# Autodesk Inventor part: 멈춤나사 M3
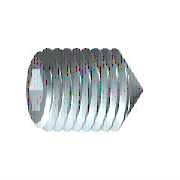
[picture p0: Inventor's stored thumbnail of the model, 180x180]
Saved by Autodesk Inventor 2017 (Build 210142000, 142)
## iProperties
Created: 2012-02
Part Number: 멈춤나사 M3
Material: 강철, 연강
Description: 6각 소켓 머리 없는 멈춤 나사
Document SubType Name: Modeling
Standard: KS B 1028
Designer: mduedu
Standards Organization: KS
Language: ko-KR
Size Designation: 원추점 M3x8
Categories: <MemberInstance><Categories><Category DisplayName="조임쇠" InternalName="e4da775c-781d-43d5-af7c-5136215cf5a6" Mnemonic="FSTN"><Category DisplayName="볼트" InternalN
Density: 7.86 g/cm^3
Mass: 0.360339 g
Surface Area: 0.888172 cm^2
Volume: 0.0458447 cm^3
Appearance: 강철
IsCustomPart: 1
Author: mduedu
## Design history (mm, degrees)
sketch "스케치1"
  geometry: L1 (0, 0)-(5.5, 0); L2 (8, 0.866)-(8, 1.5); L3 (8, 1.5)-(0, 1.5); L4 (8, 0.866)-(6, 0.866); L5 (6, 0.866)-(5.5, 0); L6 (0, -0.3)-(0, 1.8) reference; L7 (0, 1.5)-(0, 0)
  constraints: 13 end point, 3 parallel, 1 collinear, 1 perpendicular, 1 point on line
  dimensions: "d0" = 2 distance of L2.start L4.end (= INTI); "d1" = 60 deg angle of L5 L1; "d2" = 3 diameter of L3 L1 (= NND); "d3" = 1.73205 diameter of L4 L1 (= 1.1547 x SW); "d5" = 8 distance from line of L2 L3.end (= NLG)
revolve "본체" sketch "스케치1" stored, may be unused: angle "d6" = 90 deg
sketch "스케치2"
  geometry: L1 (-0.433, 0.75)-(0.433, 0.75); L2 (0.433, 0.75)-(0.866, 0); L3 (0.866, 0)-(0.433, -0.75); L4 (0.433, -0.75)-(-0.433, -0.75); L5 (-0.433, -0.75)-(-0.866, 0); L6 (-0.866, 0)-(-0.433, 0.75); 3 further points
  constraints: 12 end point, 1 coincident, 1 horizontal, 13 other
extrude "슬롯" join sketch "스케치2" taper "d7" = 0 deg; stored distance "d21" = 10
workaxis "Work Axis1"
workplane "Work Plane1"
sketch "스케치5"
  geometry: L1 (-4, -0.15)-(-2.65, -1.5) reference; L2 (-4, 0.15)-(-2.65, 1.5) reference; L3 (-2.65, 1.5)-(-4.15, 0); L4 (-2.65, -1.5)-(-4.15, 0); 1 further point
  constraints: 4 end point, 1 horizontal alignment, 1 perpendicular
node "작업점1"
body "Solid1"
feature "스레드" dims "d12" = 8 (= NLG), "d13" = 0
chamfer "모따기1" distance "d8" = 1.35 (computed from NND, SPD, FAWI); stored, may be unused: angle "d9" = 45 deg (= FAWI), second distance "d34" = 1.35 (computed from NND, SPD, FAWI)
chamfer "모따기2" distance "d10" = 0.30673 (= -0.5 x GD1 + 0.5 x NND); stored, may be unused: angle "d11" = 45 deg (= FAWI), second distance "d35" = 0.30673 (= -0.5 x GD1 + 0.5 x NND)
other parameters: "NND" = 3 [user parameter; used in 5 equation terms], "NLG" = 8 [user parameter; used in 2 equation terms], "INTI" = 2 [user parameter; used in 1 equation term], "FAWI" = 45 deg [user parameter; used in 4 equation terms], "SW" = 1.5 [user parameter; used in 2 equation terms], "GD1" = 2.38655 (= THREADDIA - 1.2269 x PTC) [user parameter; used in 2 equation terms], "d4" = 0, "FAWI1" = 45 deg [user parameter], "SPD" = 0.3 [user parameter; used in 2 equation terms], "d36" = 0, "d37" = 0, "GUL" = 0.30673 (= 0.61345 x PTC) [user parameter], "TOA" = 30 deg [user parameter], "THREADDIA" = 3 [user parameter; used in 1 equation term], "PTC" = 0.5 [user parameter; used in 4 equation terms], "GAL" = 0.30673 (= 0.61345 x PTC) [user parameter], "E0" = 1.7325 (= 1.155 x SW) [user parameter]
